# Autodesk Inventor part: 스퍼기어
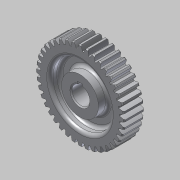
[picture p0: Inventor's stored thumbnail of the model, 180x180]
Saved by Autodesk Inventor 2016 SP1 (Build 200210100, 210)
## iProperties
Created: 2018-11
Part Number: 스퍼기어
Material: 알루미늄 6061
Document SubType Name: Modeling
Designer: mduedu
Categories: <?xml version="1.0" encoding="UTF-16"?> <MemberInstance><Categories><FamilyTemplate><FamilyTemplateParameter ValueType="xs:double" Id="1" ObjectReferenceKey="da
Density: 1 g/cm^3
Appearance: 알루미늄 - 평지
CustomPartVersion: 1
Author: mduedu
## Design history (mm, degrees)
sketch "Sketch1"
  geometry: C1 r 42 at (0, 0)
  constraints: 1 centre point
  dimensions: "d0" = 83.99905 diameter of C1 (= da_da)
extrude "Extrusion1" new body sketch "Sketch1" distance "d1" = 19 (= da_b); taper "d2" = 0 deg
workplane "Work Plane2"
sketch "Sketch2"
  geometry: C1 r 42 at (0, 0) reference; C2 r 40.05 at (0, 0)
  constraints: 1 centre point, 1 coincident
  dimensions: "d3" = 80.10038 diameter of C2 (= da_dw)
feature "피치 지름" sketch "Sketch2" dims "d4" = 10, "d5" = 0
workplane "Work Plane8"
workplane "Work Plane9"
feature "스퍼 기어" dims "da_b" = 19, "da_d" = 80, "da_aw" = 80.10038, "da_da" = 83.99905, "da_df" = 75, "da_dw" = 80.10038, angle "da_beta" = 0 deg, "da_lefttooth" = 0, "da_righttooth" = 0
sketch "스케치3"
  geometry: L1 (-42, 19)-(42, 19) reference; L2 (42, 19)-(42, 0) reference; L3 (42, 0)-(-42, 0) reference; L4 (-42, 0)-(-42, 19) reference; L5 (0, 0)-(0, 19); L6 (42, 0)-(41, 0); L7 (42, 1)-(42, 0); L8 (42, 19)-(41, 19); L9 (42, 18)-(42, 19); L10 (41, 19)-(42, 18); L11 (41, 0)-(42, 1)
  constraints: 14 end point, 2 horizontal, 2 vertical, 1 midpoint
  dimensions: "d49" = 1 distance from line of L8.end L2; "d50" = 1 horizontal distance of L8.end L9.start; "d51" = 1 horizontal distance of L6.end L7.start; "d52" = 1 horizontal distance of L6.end L7.start
revolve "회전1" sketch "스케치3" stored, may be unused: angle "d53" = 90 deg
sketch "스케치4"
  geometry: L1 (-2.5, 8.124)-(2.5, 8.124); L2 (2.5, 8.124)-(2.5, 10.8); L3 (2.5, 10.8)-(-2.5, 10.8); L4 (-2.5, 10.8)-(-2.5, 8.124); A1 r 8.5 centre (0, 0) between (-2.5, 8.124) and (2.5, 8.124); 1 further point
  constraints: 8 end point, 2 parallel, 2 point on circle, 1 centre point, 1 coincident, 1 horizontal, 1 perpendicular
  dimensions: "d54" = 17 diameter of A1; "d56" = 19.3 dimension on A1 L3; "d57" = 5 distance of L2.end L3.end
extrude "돌출2" cut sketch "스케치4" stored distance "d58" = 10; taper "d59" = 0 deg
chamfer "모따기1" distance "d60" = 1; stored, may be unused: second distance "d61" = 2, angle "d62" = 45 deg
sketch "스케치5"
  geometry: C1 r 17.5 at (0, 0); C2 r 28.5 at (0, 0); 1 further point
  constraints: 2 centre point, 2 coincident
  dimensions: "d63" = 35 diameter of C1; "d64" = 57 diameter of C2
extrude "돌출3" cut sketch "스케치5" distance "d65" = 9.5; taper "d66" = 0 deg
fillet "모깎기1" dims "d67" = 3
body "Solid1"
body "Srf1"
node "절단 모서리 투영1"
other parameters: "d16" = 80.10038 (= da_aw), "d17" = 0, "d34" = 4.5 deg (computed from da_z), "d39" = 0, "d41" = 0, "d43" = 80.10038 (= da_aw), "d46" = 80.10038 (= da_aw), "d47" = 0, "d48" = 0
